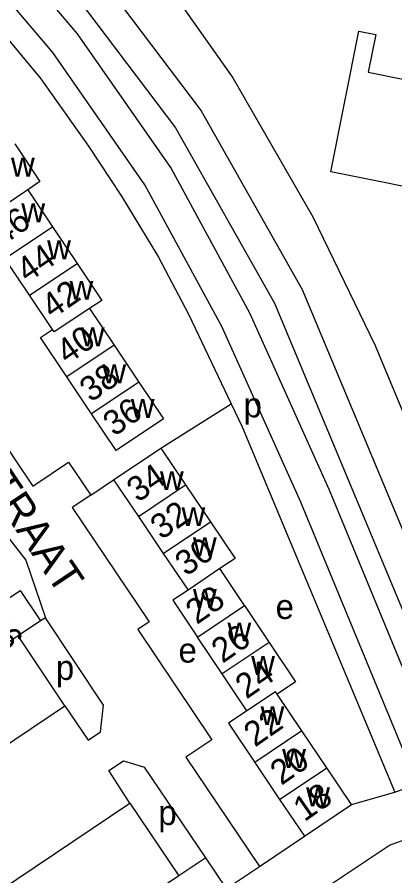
# Model space of a CAD drawing. Extents: x 158356 to 159894, y 383831 to 385260.
# Drawn here: x 159145.4 to 159206.7, y 384774.6 to 384914.1 of the extents above; entities that cross this region are included whole.
import ezdxf

# ---------------------------------------------------------------- set-up
doc = ezdxf.new("R2010")
doc.units = 0
for name, color, linetype in [('BLT_Basislijn', 7, 'Continuous'), ('BLT_Bebouwing', 7, 'Continuous'), ('BLT_Centroide', 7, 'Continuous'), ('BLT_Huisnummer', 7, 'Continuous'), ('BLT_Huisnummer_ tussenligend', 7, 'Continuous'), ('BLT_Onderverdeling_panden', 7, 'Continuous'), ('BLT_Straatnaam', 7, 'Continuous'), ('BLT_Vlakafsluiter', 7, 'Continuous')]:
    doc.layers.add(name, color=color, linetype=linetype)

msp = doc.modelspace()

# ---------------------------------------------------------------- linework, layer by layer
at = {"layer": 'BLT_Basislijn'}
for p, q in [((159168.72, 384844.07), (159180.13, 384851.27)), ((159157.33, 384836.43), (159161.05, 384838.91)), ((159149.98, 384816.51), (159149.2, 384815.99)), ((159159.38, 384802.33), (159149.98, 384816.51)), ((159153.15, 384802.19), (159145.55, 384813.54)), ((159112.6, 384774.95), (159153.15, 384802.19)), ((159153.15, 384802.19), (159156.89, 384796.64)), ((159163.7, 384786.38), (159160.25, 384791.67)), ((159176.03, 384777.52), (159166.06, 384792.25)), ((159206.69, 384788.15), (159210.31, 384789.51)), ((159199.64, 384786.17), (159206.69, 384788.15)), ((159117.17, 384755.14), (159163.7, 384786.38)), ((159163.7, 384786.38), (159171.63, 384774.59)), ((159184.71, 384776.12), (159192.01, 384781.01))]:
    msp.add_line(p, q, dxfattribs=at)
for points in [[(159078.95, 384989.43), (159096.2, 384978.92), (159116.42, 384963.88), (159133.76, 384948.84), (159152.75, 384928.69), (159175.27, 384898.83), (159191.66, 384869.8), (159265.75, 384692.27), (159279.24, 384664.38), (159294.85, 384637.65), (159324.9, 384593.77), (159342.37, 384573.46), (159351.56, 384565.34), (159355.82, 384562.28)], [(159088.7, 384977.63), (159093.4, 384974.77), (159113.29, 384959.98), (159130.3, 384945.23), (159148.93, 384925.46), (159171.08, 384896.08), (159187.16, 384867.6), (159212.7, 384806.39)], [(159092.52, 384970.65), (159101.63, 384964.29), (159117.51, 384951.56), (159136.68, 384933.05), (159155.13, 384911.34), (159170.38, 384889.46), (159183.1, 384866.05), (159196.03, 384837.26), (159209.33, 384805)], [(159210.31, 384789.51), (159191.43, 384835.28), (159178.61, 384863.83), (159166.12, 384886.83), (159151.17, 384908.29), (159133.03, 384929.63), (159114.2, 384947.8), (159098.63, 384960.29), (159088.71, 384967.21)], [(159096.29, 384958.01), (159113.68, 384943.31), (159133.2, 384923.37), (159149.21, 384904.05), (159156.95, 384893.11), (159162.31, 384884.97), (159168.33, 384875.08), (159173.19, 384865.84), (159180.13, 384851.27)], [(159065.87, 384943.31), (159073.61, 384931.81), (159076.29, 384933.59), (159084.29, 384921.69), (159088.08, 384924.2), (159104.2, 384900.2), (159106.27, 384901.6), (159122.97, 384876.77), (159122.18, 384876.19), (159147.91, 384837.85), (159153.74, 384841.77), (159157.33, 384836.43)], [(159152.96, 384940.11), (159158.01, 384934.39), (159169.6, 384919.59), (159180.4, 384904.21), (159193.4, 384881.61), (159203.52, 384860.74), (159242.25, 384767.58)], [(159180.13, 384851.27), (159181.91, 384847.53), (159206.69, 384788.15)], [(159157.33, 384836.43), (159154.31, 384834.41), (159166.83, 384815.86), (159164.99, 384814.6), (159177.01, 384796.69), (159172.78, 384793.84), (159184.71, 384776.12)], [(159142.51, 384831.49), (159143.37, 384830.22), (159146.79, 384825.88), (159149.98, 384816.51)], [(159156.89, 384796.64), (159158.92, 384797.99), (159159.38, 384802.33)], [(159160.25, 384791.67), (159162.65, 384793.27), (159166.06, 384792.25)], [(159195.44, 384772.62), (159205.81, 384779.58), (159209.65, 384780.98)]]:
    msp.add_lwpolyline(points, dxfattribs=at)
at = {"layer": 'BLT_Bebouwing'}
for p, q in [((159147.1, 384886), (159151.11, 384880.02)), ((159151.11, 384880.02), (159155.12, 384874.04)), ((159147.41, 384868.88), (159143.4, 384874.86)), ((159151.13, 384863.34), (159147.41, 384868.88)), ((159157.14, 384866.74), (159161.14, 384860.76)), ((159161.14, 384860.76), (159165.15, 384854.79)), ((159157.46, 384849.64), (159153.45, 384855.61)), ((159161.05, 384838.91), (159168.72, 384844.07)), ((159168.72, 384844.07), (159172.73, 384838.08)), ((159161.05, 384838.91), (159165.08, 384832.93)), ((159172.73, 384838.08), (159176.75, 384832.1)), ((159165.08, 384832.93), (159169.1, 384826.95)), ((159169.1, 384826.95), (159173.12, 384820.98)), ((159182.28, 384818.47), (159178.3, 384824.5)), ((159182.28, 384818.47), (159186.3, 384812.49)), ((159149.2, 384815.99), (159145.55, 384813.54)), ((159145.55, 384813.54), (159140.32, 384810.02)), ((159178.67, 384807.37), (159174.65, 384813.36)), ((159182.69, 384801.38), (159178.67, 384807.37)), ((159191.61, 384798.12), (159187.6, 384804.09)), ((159195.63, 384792.15), (159191.61, 384798.12)), ((159183.98, 384792.99), (159187.99, 384787.01)), ((159176.03, 384777.52), (159171.63, 384774.59)), ((159179.36, 384772.55), (159176.03, 384777.52)), ((159171.63, 384774.59), (159167.12, 384771.57))]:
    msp.add_line(p, q, dxfattribs=at)
for points in [[(159216.26, 384884.95), (159196.29, 384888.93), (159200.85, 384911.79)], [(159200.85, 384911.79), (159203.59, 384911.24), (159202.36, 384905.1), (159213.35, 384902.91), (159213.74, 384904.85), (159217.26, 384904.15)], [(159144.99, 384893.46), (159149.09, 384887.34), (159147.1, 384886)], [(159155.12, 384874.04), (159159.12, 384868.06), (159157.14, 384866.74)], [(159153.45, 384855.61), (159149.15, 384862.01), (159151.13, 384863.34)], [(159165.15, 384854.79), (159169.15, 384848.82), (159161.48, 384843.66), (159157.46, 384849.64)], [(159176.75, 384832.1), (159180.75, 384826.13), (159178.3, 384824.5)], [(159136.98, 384815.02), (159145.85, 384820.95), (159149.2, 384815.99)], [(159173.12, 384820.98), (159170.64, 384819.34), (159174.65, 384813.36)], [(159186.3, 384812.49), (159190.59, 384806.11), (159187.6, 384804.09)], [(159182.69, 384801.38), (159179.71, 384799.38), (159183.98, 384792.99)], [(159199.64, 384786.17), (159195.63, 384792.15)], [(159187.99, 384787.01), (159192.01, 384781.01)], [(159192.01, 384781.01), (159199.64, 384786.17)]]:
    msp.add_lwpolyline(points, dxfattribs=at)
at = {"layer": 'BLT_Onderverdeling_panden'}
for p, q in [((159143.4, 384874.86), (159151.11, 384880.02)), ((159147.41, 384868.88), (159155.12, 384874.04)), ((159161.14, 384860.76), (159153.45, 384855.61)), ((159165.15, 384854.79), (159157.46, 384849.64)), ((159165.08, 384832.93), (159172.73, 384838.08)), ((159169.1, 384826.95), (159176.75, 384832.1)), ((159178.3, 384824.5), (159173.12, 384820.98)), ((159174.65, 384813.36), (159182.28, 384818.47)), ((159186.3, 384812.49), (159178.67, 384807.37)), ((159191.61, 384798.12), (159183.98, 384792.99)), ((159187.99, 384787.01), (159195.63, 384792.15))]:
    msp.add_line(p, q, dxfattribs=at)
for points in [[(159147.1, 384886), (159141.37, 384882.16), (159141.08, 384882.6)], [(159157.14, 384866.74), (159151.41, 384862.93), (159151.13, 384863.34)], [(159187.6, 384804.09), (159187.33, 384804.49), (159182.69, 384801.38)]]:
    msp.add_lwpolyline(points, dxfattribs=at)
at = {"layer": 'BLT_Vlakafsluiter'}
msp.add_line((159179.36, 384772.55), (159184.71, 384776.12), dxfattribs=at)

# ---------------------------------------------------------------- texts
at = {"layer": 'BLT_Centroide'}
for s, p in [('w', (159144.38, 384888.16)), ('w', (159146.06, 384880.74)), ('w', (159150.25, 384874.72)), ('w', (159153.89, 384868.15)), ('w', (159155.71, 384860.59)), ('w', (159159.21, 384854.57)), ('w', (159163.83, 384848.97)), ('p', (159182.14, 384849.06)), ('w', (159168.56, 384837.24)), ('w', (159172.06, 384831.38)), ('w', (159173.92, 384826.5)), ('w', (159173.92, 384818.09)), ('e', (159187.34, 384816.3)), ('w', (159179.52, 384812.65)), ('e', (159171.58, 384809.22)), ('p', (159151.67, 384806.41)), ('w', (159183.37, 384807.22)), ('w', (159184.9, 384799.06)), ('w', (159188.4, 384792.09)), ('w', (159192.29, 384785.87)), ('p', (159168.3, 384782.84))]:
    msp.add_text(s, height=4, dxfattribs=at).set_placement(p)
at = {"layer": 'BLT_Huisnummer'}
for s, rotation, p in [('44', 34.8063, (159147.06, 384870.82)), ('40', 34.8063, (159153.54, 384857.55)), ('36', 34.8063, (159161.13, 384845.85)), ('34', 34.8063, (159164.98, 384835.13)), ('30', 34.8063, (159172.82, 384823.14)), ('16', 304.8063, (159139.94, 384815.64)), ('26', 34.8063, (159178.72, 384809.01)), ('22', 34.8063, (159183.98, 384795.4)), ('18', 34.8063, (159192, 384783.28))]:
    msp.add_text(s, height=4, rotation=rotation, dxfattribs=at).set_placement(p)
at = {"layer": 'BLT_Huisnummer_ tussenligend'}
for s, p in [('46', (159142.99, 384876.83)), ('42', (159151.11, 384864.95)), ('38', (159157.33, 384851.39)), ('32', (159168.81, 384829.07)), ('28', (159174.54, 384815.31)), ('24', (159182.6, 384803.2)), ('20', (159188.26, 384789.18))]:
    msp.add_text(s, height=4, rotation=34.8063, dxfattribs=at).set_placement(p)
at = {"layer": 'BLT_Straatnaam'}
msp.add_text('DEFLECTIESPOELSTRAAT', height=5, rotation=303.8882, dxfattribs=at).set_placement((159104.66, 384890.92))

doc.saveas('drawing.dxf')
